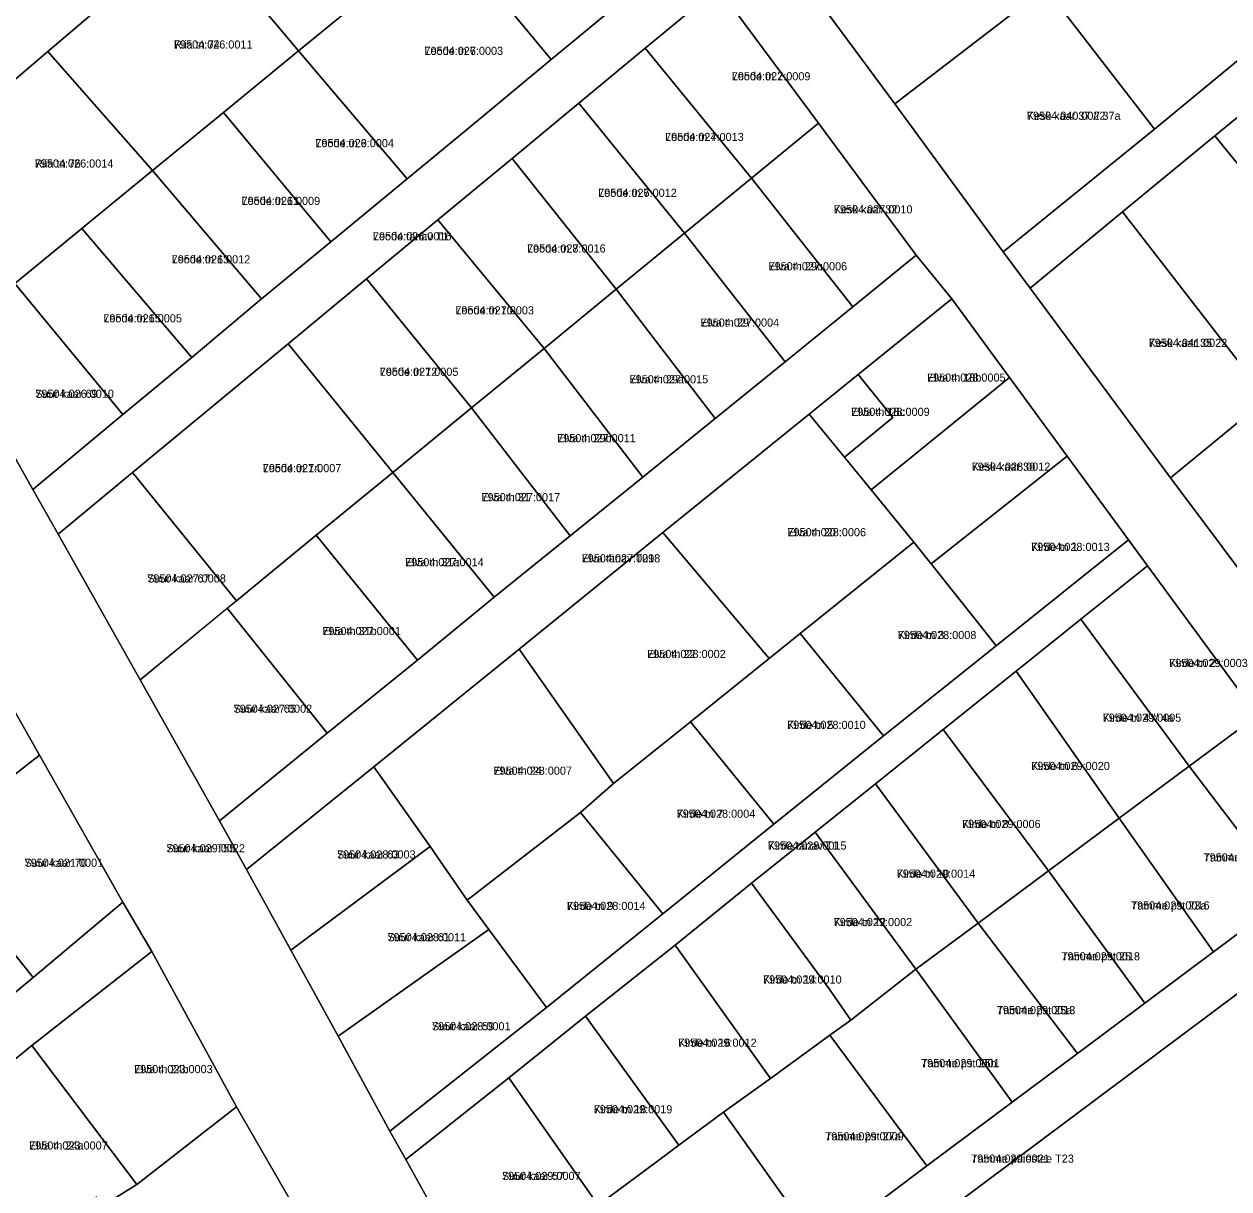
# Model space of a CAD drawing. Extents: x 643847 to 663718, y 6468443 to 6482775.
# Drawn here: x 658107 to 658329.4, y 6472418.9 to 6472633.9 of the extents above; entities that cross this region are included whole.
import ezdxf

# ---------------------------------------------------------------- set-up
doc = ezdxf.new("R2010")
doc.units = 0
for name, color, linetype in [('L_AADRESS', 7, 'Continuous'), ('PIIR', 7, 'Continuous'), ('TUNNUS', 7, 'Continuous')]:
    doc.layers.add(name, color=color, linetype=linetype)

msp = doc.modelspace()

# ---------------------------------------------------------------- linework, layer by layer
at = {"layer": 'PIIR'}
for points in [[(658476.41, 6472746.4), (658481.77, 6472740.15), (658462.03, 6472724), (658457.54, 6472720.31), (658446.42, 6472711.21), (658425.53, 6472694.11), (658401.27, 6472674.16), (658376.23, 6472653.7), (658351.1, 6472633.18), (658326.77, 6472613.25), (658309.72, 6472599.21), (658292.66, 6472585.16), (658287.71, 6472591.85), (658315.65, 6472614.5), (658343.41, 6472637.4), (658365.01, 6472655.1), (658368.49, 6472657.96), (658393.31, 6472678.35), (658418.43, 6472699.1), (658443.25, 6472719.42), (658459.77, 6472732.55)], [(658315.64, 6472614.51), (658295.54, 6472640.57), (658278.01, 6472663.31), (658305.02, 6472684.01), (658343.41, 6472637.4)], [(658152.09, 6472663.45), (658171.29, 6472640.07), (658157.67, 6472628.92), (658138.45, 6472651.84)], [(658278.01, 6472663.28), (658295.54, 6472640.57), (658267.71, 6472619.13), (658250.33, 6472642.71)], [(658204.27, 6472627.33), (658184.67, 6472651.04), (658197.95, 6472661.91), (658217.67, 6472638.43)], [(658138.45, 6472651.84), (658157.67, 6472628.92), (658143.83, 6472617.53), (658130.72, 6472606.88), (658111.44, 6472628.81)], [(658191.11, 6472616.42), (658177.75, 6472605.34), (658157.67, 6472628.92), (658171.29, 6472640.07), (658184.67, 6472651.04), (658204.27, 6472627.33)], [(658229.44, 6472648.2), (658235.1, 6472640.57), (658221.66, 6472629.43), (658209.41, 6472619.29), (658197.08, 6472609.08), (658183.41, 6472597.75), (658170.24, 6472586.84), (658155.74, 6472574.87), (658127.02, 6472551.09), (658113.3, 6472539.73), (658108.64, 6472548.01), (658125.25, 6472561.8), (658137.99, 6472572.37), (658150.86, 6472583.16), (658163.62, 6472593.66), (658177.75, 6472605.34), (658191.11, 6472616.42), (658204.27, 6472627.33), (658217.67, 6472638.43)], [(658235.1, 6472640.57), (658253.63, 6472615.57), (658241.26, 6472605.43), (658221.66, 6472629.43)], [(658295.54, 6472640.57), (658315.65, 6472614.5), (658287.71, 6472591.85), (658267.71, 6472619.13)], [(658351.1, 6472633.18), (658399.72, 6472574.6), (658374.9, 6472554.22), (658354.26, 6472579.45), (658326.77, 6472613.26)], [(658221.66, 6472629.43), (658241.26, 6472605.43), (658228.89, 6472595.28), (658209.41, 6472619.29)], [(658111.44, 6472628.81), (658130.72, 6472606.88), (658118.46, 6472596.77), (658117.69, 6472596.14), (658105.32, 6472586), (658087.17, 6472608.12)], [(658163.62, 6472593.66), (658143.83, 6472617.53), (658157.67, 6472628.92), (658177.75, 6472605.34)], [(658209.41, 6472619.29), (658228.89, 6472595.28), (658216.29, 6472584.94), (658197.08, 6472609.08)], [(658150.86, 6472583.16), (658130.72, 6472606.88), (658143.83, 6472617.53), (658163.62, 6472593.66)], [(658271.68, 6472591.23), (658259.95, 6472581.72), (658241.26, 6472605.43), (658253.63, 6472615.57)], [(658309.72, 6472599.21), (658326.77, 6472613.25), (658354.26, 6472579.45), (658336.44, 6472564.79)], [(658197.08, 6472609.08), (658216.29, 6472584.94), (658202.99, 6472574.02), (658183.41, 6472597.75)], [(658137.99, 6472572.37), (658117.69, 6472596.14), (658118.46, 6472596.77), (658130.72, 6472606.88), (658150.86, 6472583.16)], [(658247.45, 6472571.57), (658228.89, 6472595.28), (658241.26, 6472605.43), (658259.95, 6472581.72)], [(658292.66, 6472585.16), (658309.72, 6472599.21), (658336.44, 6472564.79), (658318.61, 6472550.13)], [(658125.25, 6472561.8), (658105.32, 6472586), (658117.69, 6472596.14), (658137.99, 6472572.37)], [(658183.41, 6472597.75), (658202.99, 6472574.02), (658189.61, 6472563.05), (658170.24, 6472586.84)], [(658234.55, 6472561.1), (658216.29, 6472584.94), (658228.89, 6472595.28), (658247.45, 6472571.57)], [(658271.68, 6472591.23), (658278.22, 6472583.17), (658260.96, 6472569.22), (658251.9, 6472561.89), (658224.88, 6472540.04), (658198.4, 6472518.51), (658171.57, 6472496.82), (658148.09, 6472477.84), (658143.09, 6472486.85), (658162.96, 6472502.99), (658179.62, 6472516.51), (658193.76, 6472528.13), (658207.82, 6472539.41), (658221.2, 6472550.26), (658234.55, 6472561.1), (658247.45, 6472571.57), (658259.95, 6472581.72)], [(658092.96, 6472575.85), (658105.32, 6472586), (658125.25, 6472561.8), (658108.64, 6472548.01)], [(658170.24, 6472586.84), (658189.61, 6472563.05), (658175.07, 6472551.14), (658155.74, 6472574.87)], [(658221.2, 6472550.26), (658202.99, 6472574.02), (658216.29, 6472584.94), (658234.55, 6472561.1)], [(658278.22, 6472583.17), (658288.88, 6472568.65), (658263.32, 6472547.92), (658258.42, 6472553.92), (658267.35, 6472561.3), (658260.96, 6472569.22)], [(658318.61, 6472550.13), (658336.44, 6472564.79), (658354.26, 6472579.45), (658374.9, 6472554.22), (658337.65, 6472524.66)], [(658155.74, 6472574.87), (658175.07, 6472551.14), (658160.94, 6472539.53), (658146.25, 6472527.46), (658127.02, 6472551.09)], [(658207.82, 6472539.41), (658189.61, 6472563.05), (658202.99, 6472574.02), (658221.2, 6472550.26)], [(658260.96, 6472569.22), (658267.35, 6472561.3), (658258.42, 6472553.92), (658251.9, 6472561.89)], [(658299.52, 6472554.14), (658274.41, 6472534.25), (658271.24, 6472538.24), (658263.32, 6472547.92), (658288.88, 6472568.65)], [(658193.76, 6472528.13), (658175.07, 6472551.14), (658189.61, 6472563.05), (658207.82, 6472539.41)], [(658251.9, 6472561.89), (658263.32, 6472547.92), (658271.24, 6472538.24), (658250.25, 6472521.39), (658244.54, 6472516.81), (658224.88, 6472540.04)], [(658286.43, 6472519.15), (658283.93, 6472522.27), (658274.41, 6472534.25), (658299.52, 6472554.14), (658310.85, 6472538.69)], [(658113.3, 6472539.73), (658127.02, 6472551.09), (658146.25, 6472527.46), (658128.44, 6472512.85)], [(658179.62, 6472516.51), (658160.94, 6472539.53), (658175.07, 6472551.14), (658193.76, 6472528.13)], [(658162.96, 6472502.99), (658144.53, 6472526.06), (658146.25, 6472527.46), (658160.94, 6472539.53), (658179.62, 6472516.51)], [(658310.85, 6472538.69), (658314.37, 6472533.9), (658302.04, 6472524.03), (658290.11, 6472514.46), (658276.66, 6472503.68), (658264.17, 6472493.66), (658253.02, 6472484.73), (658241.24, 6472475.32), (658227.19, 6472463.9), (658210.66, 6472450.76), (658196.47, 6472439.38), (658177.51, 6472424.34), (658174.55, 6472429.55), (658203.41, 6472452.38), (658224.88, 6472469.67), (658245.39, 6472486.2), (658265.65, 6472502.52), (658286.43, 6472519.15)], [(658244.54, 6472516.81), (658229.99, 6472505.13), (658215.8, 6472493.73), (658198.4, 6472518.51), (658224.88, 6472540.04)], [(658265.65, 6472502.52), (658250.25, 6472521.39), (658271.24, 6472538.24), (658274.41, 6472534.25), (658283.93, 6472522.27), (658286.43, 6472519.15)], [(658314.37, 6472533.9), (658334.64, 6472506.29), (658322.03, 6472496.94), (658302.04, 6472524.03)], [(658128.44, 6472512.85), (658144.53, 6472526.06), (658162.96, 6472502.99), (658143.09, 6472486.85)], [(658302.04, 6472524.03), (658322.03, 6472496.94), (658309.11, 6472487.34), (658290.11, 6472514.46)], [(658245.39, 6472486.2), (658229.99, 6472505.13), (658244.54, 6472516.81), (658250.25, 6472521.39), (658265.65, 6472502.52)], [(658198.4, 6472518.51), (658215.8, 6472493.73), (658209.72, 6472488.38), (658188.8, 6472472.17), (658181.95, 6472482.12), (658171.57, 6472496.82)], [(658109.9, 6472498.98), (658089, 6472482.59), (658072.35, 6472503.43), (658099.8, 6472516.73)], [(658276.66, 6472503.68), (658290.11, 6472514.46), (658309.11, 6472487.34), (658296.08, 6472477.63)], [(658224.88, 6472469.67), (658209.72, 6472488.38), (658215.8, 6472493.73), (658229.99, 6472505.13), (658245.39, 6472486.2)], [(658353.18, 6472482.57), (658340.27, 6472472.93), (658322.03, 6472496.94), (658334.64, 6472506.29)], [(658276.66, 6472503.68), (658296.08, 6472477.63), (658283.07, 6472467.97), (658264.17, 6472493.66)], [(658125.26, 6472471.82), (658108.73, 6472457.89), (658089, 6472482.59), (658109.9, 6472498.98)], [(658148.09, 6472477.84), (658171.57, 6472496.82), (658181.95, 6472482.12), (658156.27, 6472462.94)], [(658326.51, 6472462.64), (658309.11, 6472487.34), (658322.03, 6472496.94), (658340.27, 6472472.93)], [(658264.17, 6472493.66), (658283.07, 6472467.97), (658271.59, 6472459.45), (658253.02, 6472484.73)], [(658203.41, 6472452.38), (658192.78, 6472466.79), (658188.8, 6472472.17), (658209.72, 6472488.38), (658224.88, 6472469.67)], [(658313.86, 6472453.18), (658296.08, 6472477.63), (658309.11, 6472487.34), (658326.51, 6472462.64)], [(658253.02, 6472484.73), (658271.59, 6472459.45), (658259.62, 6472450.05), (658255.63, 6472455.84), (658241.24, 6472475.32)], [(658095.25, 6472446.71), (658075.4, 6472471.58), (658089, 6472482.59), (658108.73, 6472457.89)], [(658156.27, 6472462.94), (658181.95, 6472482.12), (658188.8, 6472472.17), (658192.78, 6472466.79), (658164.99, 6472447.09)], [(658326.51, 6472462.64), (658340.27, 6472472.93), (658353.18, 6472482.57), (658357.83, 6472475.04), (658210.47, 6472364.93), (658205.91, 6472372.86), (658219.62, 6472382.69), (658230.27, 6472390.66), (658253.73, 6472408.21), (658273.62, 6472423.17), (658289.36, 6472434.94), (658301.45, 6472443.89), (658313.86, 6472453.18)], [(658313.86, 6472453.18), (658301.45, 6472443.89), (658283.07, 6472467.97), (658296.08, 6472477.63)], [(658210.47, 6472364.93), (658357.83, 6472475.04), (658405.85, 6472410.35), (658250.88, 6472294.58)], [(658244.78, 6472439.28), (658227.19, 6472463.9), (658241.24, 6472475.32), (658255.63, 6472455.84), (658259.62, 6472450.05), (658255.75, 6472447.3)], [(658289.36, 6472434.94), (658271.59, 6472459.45), (658283.07, 6472467.97), (658301.45, 6472443.89)], [(658164.99, 6472447.09), (658192.78, 6472466.79), (658203.41, 6472452.38), (658174.55, 6472429.55)], [(658127.84, 6472419.7), (658108.45, 6472445.36), (658130.61, 6472462.71), (658146.22, 6472434.06)], [(658227.19, 6472463.9), (658244.78, 6472439.28), (658236.11, 6472433.09), (658227.84, 6472426.95), (658210.66, 6472450.76)], [(658273.62, 6472423.17), (658255.75, 6472447.3), (658259.62, 6472450.05), (658271.59, 6472459.45), (658289.36, 6472434.94)], [(658196.47, 6472439.38), (658210.66, 6472450.76), (658227.84, 6472426.95), (658223.91, 6472424.01), (658212.95, 6472415.88)], [(658253.73, 6472408.21), (658236.11, 6472433.09), (658244.78, 6472439.28), (658255.75, 6472447.3), (658273.62, 6472423.17)], [(658108.45, 6472445.36), (658127.84, 6472419.7), (658121.81, 6472415.96), (658120.4, 6472417.46), (658106.12, 6472405.88), (658090.87, 6472425.41), (658088.1, 6472428.77)], [(658177.51, 6472424.34), (658196.47, 6472439.38), (658212.95, 6472415.88), (658201.56, 6472407.41), (658191.13, 6472399.66)], [(658146.22, 6472434.06), (658156.29, 6472416.63), (658134.18, 6472398.99), (658121.81, 6472415.96), (658127.84, 6472419.7)], [(658230.27, 6472390.66), (658212.95, 6472415.88), (658223.91, 6472424.01), (658227.84, 6472426.95), (658236.11, 6472433.09), (658253.73, 6472408.21)]]:
    msp.add_lwpolyline(points, close=True, dxfattribs=at)
for points in [[(658095.63, 6472655.21), (658122.04, 6472677.69), (658138.45, 6472651.84), (658111.44, 6472628.81), (658087.17, 6472608.12)], [(658250.33, 6472642.71), (658267.71, 6472619.13), (658287.71, 6472591.85), (658292.66, 6472585.16), (658318.61, 6472550.13), (658337.65, 6472524.66)], [(658334.64, 6472506.29), (658314.37, 6472533.9), (658310.85, 6472538.69), (658299.52, 6472554.14), (658288.88, 6472568.65), (658278.22, 6472583.17), (658271.68, 6472591.23), (658253.63, 6472615.57), (658235.1, 6472640.57)], [(658092.96, 6472575.85), (658108.64, 6472548.01), (658113.3, 6472539.73), (658128.44, 6472512.85), (658143.09, 6472486.85), (658148.09, 6472477.84), (658156.27, 6472462.94), (658164.99, 6472447.09), (658174.55, 6472429.55), (658177.51, 6472424.34), (658191.13, 6472399.66), (658205.91, 6472372.86), (658188.35, 6472359.53), (658177.01, 6472379.69), (658166.6, 6472398.17), (658156.29, 6472416.63), (658146.22, 6472434.06), (658130.61, 6472462.71), (658125.26, 6472471.82), (658109.9, 6472498.98), (658099.8, 6472516.73)], [(658095.25, 6472446.71), (658108.73, 6472457.89), (658125.26, 6472471.82), (658130.61, 6472462.71), (658108.45, 6472445.36), (658088.1, 6472428.77)]]:
    msp.add_lwpolyline(points, dxfattribs=at)

# ---------------------------------------------------------------- texts
at = {"layer": 'L_AADRESS'}
for s, p in [('Riia tn 74', (658134.69, 6472629.36)), ('Loode tn 7', (658180.93, 6472628.19)), ('Loode tn 2', (658237.64, 6472623.5)), ('Kesk kaar 37 // 37a', (658292.09, 6472616.21)), ('Loode tn 4', (658225.33, 6472612.3)), ('Loode tn 9', (658160.79, 6472611.16)), ('Riia tn 76', (658109.01, 6472607.4)), ('Loode tn 6', (658212.98, 6472601.99)), ('Loode tn 11', (658147.17, 6472600.5)), ('Kesk kaar 32', (658256.47, 6472598.94)), ('Loode tänav T1', (658171.41, 6472593.96)), ('Loode tn 8', (658199.85, 6472591.71)), ('Loode tn 13', (658134.27, 6472589.71)), ('Elva tn 29c', (658244.42, 6472588.43)), ('Loode tn 10', (658186.62, 6472580.3)), ('Loode tn 15', (658121.66, 6472578.83)), ('Elva tn 29', (658231.87, 6472578.04)), ('Kesk kaar 35', (658314.55, 6472574.3)), ('Loode tn 12', (658172.68, 6472568.96)), ('Elva tn 18b', (658273.65, 6472567.89)), ('Elva tn 29a', (658218.77, 6472567.57)), ('Suur kaar 69', (658109.11, 6472564.9)), ('Elva tn 18c', (658259.65, 6472561.57)), ('Elva tn 29b', (658205.41, 6472556.71)), ('Loode tn 14', (658151.08, 6472551.17)), ('Kesk kaar 30', (658281.9, 6472551.45)), ('Elva tn 31', (658191.45, 6472545.82)), ('Elva tn 20', (658247.9, 6472539.35)), ('Kirde tn 1', (658292.86, 6472536.65)), ('Elva tänav T29', (658209.93, 6472534.54)), ('Elva tn 31a', (658177.35, 6472533.82)), ('Suur kaar 67', (658129.77, 6472530.82)), ('Elva tn 31b', (658162.07, 6472521.11)), ('Kirde tn 3', (658268.26, 6472520.38)), ('Elva tn 22', (658222.01, 6472516.88)), ('Kirde tn 2', (658318.34, 6472515.22)), ('Suur kaar 65', (658145.7, 6472506.78)), ('Kirde tn 5', (658247.84, 6472503.79)), ('Kirde tn 4 // 4a', (658306.07, 6472505.12)), ('Elva tn 24', (658193.64, 6472495.34)), ('Kirde tn 6', (658292.88, 6472496.21)), ('Kirde tn 7', (658227.46, 6472487.4)), ('Kirde tn 8', (658280.12, 6472485.5)), ('Kirde tänav T1', (658244.29, 6472481.52)), ('Suur kaar T55', (658133.29, 6472481.02)), ('Suur kaar 63', (658164.78, 6472479.88)), ('Tamme pst 23', (658324.69, 6472479.33)), ('Suur kaar 70', (658107.13, 6472478.35)), ('Kirde tn 10', (658268.05, 6472476.33)), ('Kirde tn 9', (658207.21, 6472470.38)), ('Tamme pst 23a', (658311.29, 6472470.47)), ('Kirde tn 12', (658256.42, 6472467.4)), ('Suur kaar 61', (658174.1, 6472464.61)), ('Tamme pst 25', (658298.46, 6472461.08)), ('Kirde tn 14', (658243.4, 6472456.8)), ('Tamme pst 25a', (658286.52, 6472451.15)), ('Suur kaar 59', (658182.3, 6472448.17)), ('Kirde tn 16', (658227.72, 6472445.14)), ('Tamme pst 25b', (658272.55, 6472441.36)), ('Elva tn 24b', (658127.34, 6472440.26)), ('Kirde tn 18', (658212.16, 6472432.85)), ('Tamme pst 27a', (658254.86, 6472427.86)), ('Elva tn 24a', (658107.97, 6472426.17)), ('Tamme puiestee T23', (658281.79, 6472423.75)), ('Suur kaar 57', (658195.23, 6472420.55))]:
    msp.add_text(s, height=1.5, dxfattribs=at).set_placement(p)
at = {"layer": 'TUNNUS'}
for s, p in [('79504:026:0011', (658134.69, 6472629.36)), ('79504:026:0003', (658180.93, 6472628.19)), ('79504:027:0009', (658237.64, 6472623.5)), ('79504:040:0022', (658292.09, 6472616.21)), ('79504:027:0013', (658225.33, 6472612.3)), ('79504:026:0004', (658160.79, 6472611.16)), ('79504:026:0014', (658109.01, 6472607.4)), ('79504:027:0012', (658212.98, 6472601.99)), ('79504:026:0009', (658147.17, 6472600.5)), ('79504:027:0010', (658256.47, 6472598.94)), ('79504:026:0016', (658171.41, 6472593.96)), ('79504:027:0016', (658199.85, 6472591.71)), ('79504:026:0012', (658134.27, 6472589.71)), ('79504:027:0006', (658244.42, 6472588.43)), ('79504:027:0003', (658186.62, 6472580.3)), ('79504:026:0005', (658121.66, 6472578.83)), ('79504:027:0004', (658231.87, 6472578.04)), ('79504:041:0022', (658314.55, 6472574.3)), ('79504:027:0005', (658172.68, 6472568.96)), ('79504:028:0005', (658273.65, 6472567.89)), ('79504:027:0015', (658218.77, 6472567.57)), ('79504:026:0010', (658109.11, 6472564.9)), ('79504:028:0009', (658259.65, 6472561.57)), ('79504:027:0011', (658205.41, 6472556.71)), ('79504:027:0007', (658151.08, 6472551.17)), ('79504:028:0012', (658281.9, 6472551.45)), ('79504:027:0017', (658191.45, 6472545.82)), ('79504:028:0006', (658247.9, 6472539.35)), ('79504:027:0018', (658209.93, 6472534.54)), ('79504:028:0013', (658292.86, 6472536.65)), ('79504:027:0014', (658177.35, 6472533.82)), ('79504:027:0008', (658129.77, 6472530.82)), ('79504:027:0001', (658162.07, 6472521.11)), ('79504:028:0008', (658268.26, 6472520.38)), ('79504:028:0002', (658222.01, 6472516.88)), ('79504:029:0003', (658318.34, 6472515.22)), ('79504:027:0002', (658145.7, 6472506.78)), ('79504:028:0010', (658247.84, 6472503.79)), ('79504:029:0005', (658306.07, 6472505.12)), ('79504:028:0007', (658193.64, 6472495.34)), ('79504:029:0020', (658292.88, 6472496.21)), ('79504:028:0004', (658227.46, 6472487.4)), ('79504:029:0006', (658280.12, 6472485.5)), ('79504:028:0015', (658244.29, 6472481.52)), ('79504:029:0022', (658133.29, 6472481.02)), ('79504:028:0003', (658164.78, 6472479.88)), ('79504:029:0011', (658324.69, 6472479.33)), ('79504:021:0001', (658107.13, 6472478.35)), ('79504:029:0014', (658268.05, 6472476.33)), ('79504:028:0014', (658207.21, 6472470.38)), ('79504:029:0016', (658311.29, 6472470.47)), ('79504:029:0002', (658256.42, 6472467.4)), ('79504:028:0011', (658174.1, 6472464.61)), ('79504:029:0018', (658298.46, 6472461.08)), ('79504:029:0010', (658243.4, 6472456.8)), ('79504:029:0013', (658286.52, 6472451.15)), ('79504:028:0001', (658182.3, 6472448.17)), ('79504:029:0012', (658227.72, 6472445.14)), ('79504:029:0001', (658272.55, 6472441.36)), ('79504:023:0003', (658127.34, 6472440.26)), ('79504:029:0019', (658212.16, 6472432.85)), ('79504:029:0009', (658254.86, 6472427.86)), ('79504:023:0007', (658107.97, 6472426.17)), ('79504:029:0021', (658281.79, 6472423.75)), ('79504:029:0007', (658195.23, 6472420.55))]:
    msp.add_text(s, height=1.5, dxfattribs=at).set_placement(p)

doc.saveas('drawing.dxf')
